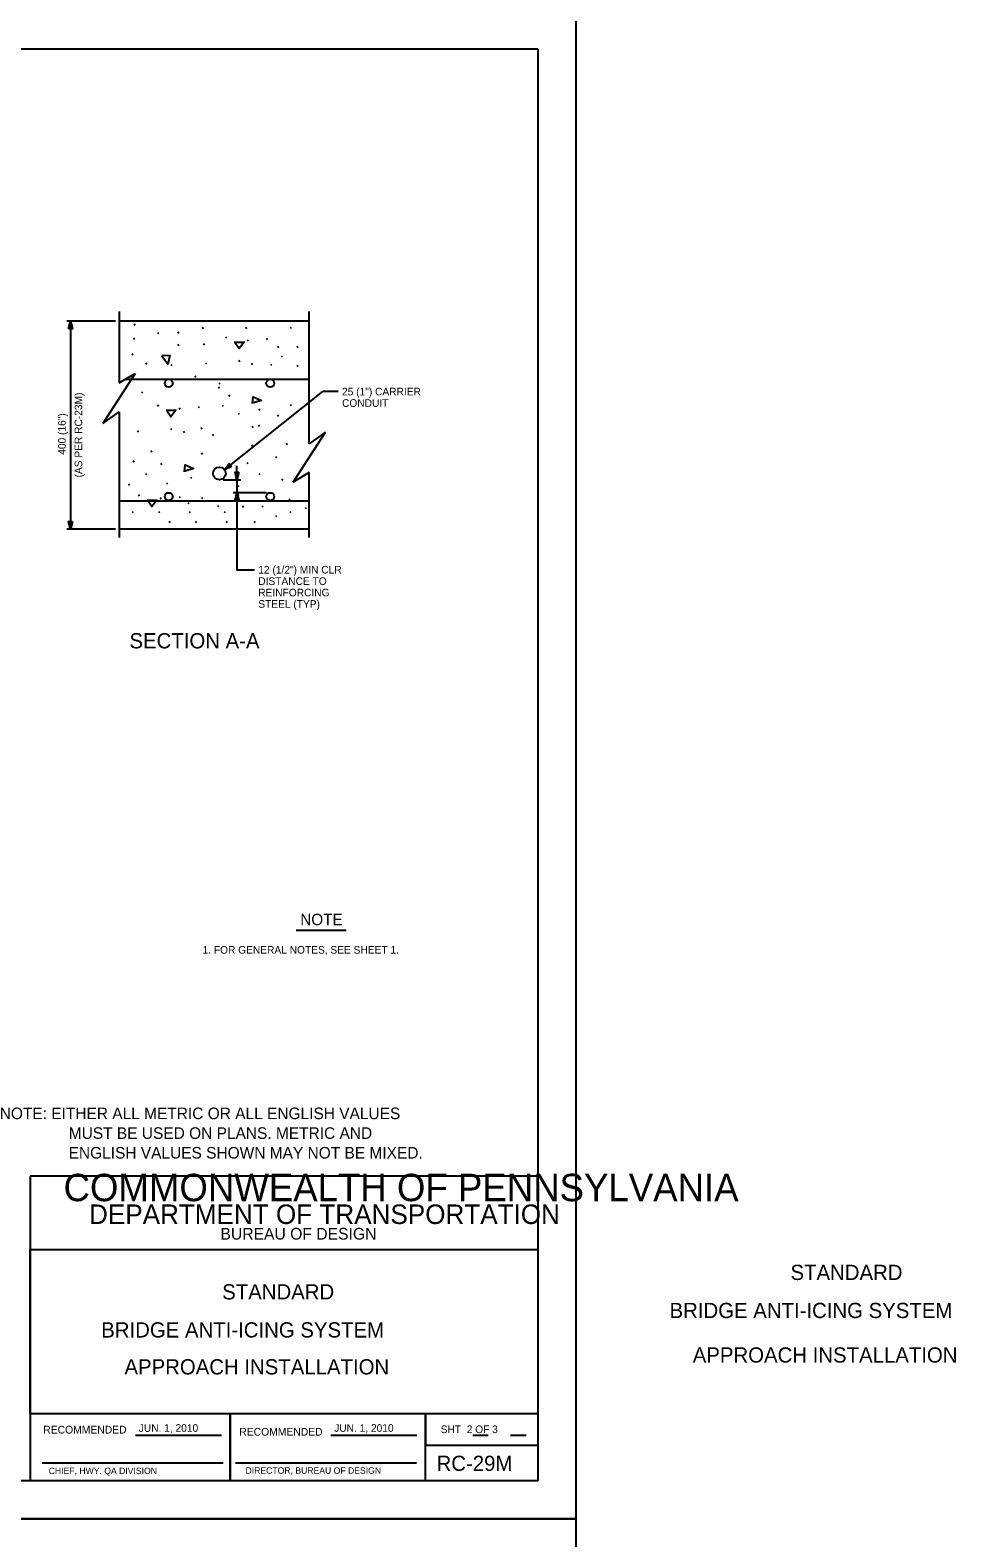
# Model space of a CAD drawing. Extents: x 3239 to 4230, y -4276 to -2494.
# Drawn here: x 3865 to 4230, y -3690 to -3096 of the extents above; entities that cross this region are included whole.
import ezdxf

# ---------------------------------------------------------------- set-up
doc = ezdxf.new("R2010")
doc.units = 0
for name, color, linetype in [('1', 7, 'Continuous'), ('2', 7, 'Continuous'), ('40', 7, 'Continuous'), ('PLT-BNDY', 7, 'Continuous')]:
    doc.layers.add(name, color=color, linetype=linetype)

msp = doc.modelspace()

# ---------------------------------------------------------------- linework, layer by layer
at = {"layer": '1'}
for p, q in [((4065.03, -3547.29), (3865.03, -3547.29)), ((3865.03, -3547.29), (3865.03, -3667.29)), ((3865.03, -3640.93), (3865.03, -3576.25)), ((3865.03, -3576.25), (4065.03, -3576.25)), ((4065.03, -3640.93), (3865.03, -3640.93)), ((3943.83, -3667.29), (3943.83, -3640.93)), ((3943.83, -3640.93), (3943.83, -3667.29)), ((4020.83, -3667.29), (4020.83, -3640.93)), ((4020.83, -3640.93), (4020.83, -3653.25)), ((3906.49, -3649.3), (3940.38, -3649.3)), ((3983.49, -3649.3), (4017.36, -3649.3)), ((4039.41, -3649.33), (4045.55, -3649.33)), ((4054.27, -3649.33), (4060.43, -3649.33)), ((4020.83, -3653.25), (4065.03, -3653.25)), ((3869.79, -3660.29), (3941.04, -3660.29)), ((3945.96, -3660.29), (4017.3, -3660.29))]:
    msp.add_line(p, q, dxfattribs=at)
at = {"layer": '2'}
for p, q in [((4065.03, -3103.29), (3279.03, -3103.29)), ((4065.03, -3103.29), (4065.03, -3667.29)), ((3900.15, -3206.57), (3900.15, -3234.8)), ((3974.95, -3258.76), (3974.95, -3206.57)), ((3898.65, -3210.43), (3879.45, -3210.43)), ((3880.95, -3210.43), (3880.95, -3292.43)), ((3974.95, -3210.43), (3900.15, -3210.43)), ((3906.02, -3211.97), (3906.49, -3211.6)), ((3932.81, -3213.26), (3933.28, -3212.89)), ((3949.89, -3213.26), (3950.36, -3212.89)), ((3967.55, -3213.26), (3968.02, -3212.89)), ((3905.78, -3217.46), (3906.24, -3217.09)), ((3915.28, -3215.28), (3915.74, -3214.9)), ((3923.25, -3215.13), (3923.71, -3214.76)), ((3933.38, -3219.8), (3933.85, -3219.43)), ((3942.07, -3217.03), (3942.54, -3216.66)), ((3950.65, -3218.21), (3951.11, -3217.84)), ((3958.19, -3217.65), (3958.66, -3217.28)), ((3905.11, -3223.64), (3905.58, -3223.26)), ((3923.25, -3219.98), (3923.71, -3219.61)), ((3962.51, -3220.74), (3962.97, -3220.37)), ((3964.03, -3224.49), (3964.49, -3224.11)), ((3970.11, -3220.74), (3970.58, -3220.37)), ((3906.39, -3231.01), (3893.65, -3250.75)), ((3900.15, -3234.8), (3906.39, -3231.01)), ((3910.67, -3227.42), (3911.14, -3227.05)), ((3920.54, -3227.9), (3921.01, -3227.53)), ((3934.2, -3227.21), (3934.66, -3226.83)), ((3947.29, -3226.32), (3947.76, -3225.95)), ((3952.3, -3227.49), (3952.76, -3227.12)), ((3959.82, -3227.76), (3960.28, -3227.39)), ((3970.11, -3228.23), (3970.58, -3227.86)), ((3902.83, -3233.25), (3974.95, -3233.25)), ((3929.96, -3232.47), (3930.42, -3232.1)), ((3939.28, -3236.85), (3939.74, -3236.48)), ((3939.46, -3235.08), (3939.93, -3234.71)), ((3908.99, -3238.71), (3909.45, -3238.34)), ((3941.61, -3268.95), (3980.42, -3238.19)), ((3943.37, -3240.01), (3943.84, -3239.64)), ((3986.42, -3238.19), (3980.42, -3238.19)), ((3893.65, -3250.75), (3900.15, -3246.13)), ((3900.15, -3246.13), (3900.15, -3295.62)), ((3915.23, -3243.87), (3915.7, -3243.5)), ((3923.81, -3245.05), (3924.27, -3244.68)), ((3931.35, -3244.49), (3931.82, -3244.12)), ((3940.76, -3243.93), (3941.23, -3243.56)), ((3947.1, -3247.1), (3947.56, -3246.72)), ((3955.16, -3245.47), (3955.63, -3245.09)), ((3962.51, -3247.89), (3962.97, -3247.52)), ((3967.58, -3243.63), (3968.04, -3243.25)), ((3907.36, -3254.04), (3907.82, -3253.67)), ((3920.45, -3253.16), (3920.92, -3252.79)), ((3925.46, -3254.33), (3925.93, -3253.95)), ((3932.28, -3252.78), (3932.75, -3252.41)), ((3936.93, -3255.46), (3937.4, -3255.08)), ((3952.55, -3252.36), (3953.02, -3251.99)), ((3955.07, -3251.8), (3955.53, -3251.43)), ((3968.71, -3273.88), (3981.44, -3254.14)), ((3981.44, -3254.14), (3974.95, -3258.76)), ((3952.3, -3259.66), (3952.76, -3259.28)), ((3965.95, -3258.96), (3966.41, -3258.58)), ((3905.66, -3265.8), (3906.12, -3265.43)), ((3912.62, -3261.92), (3913.09, -3261.55)), ((3916.53, -3266.85), (3917, -3266.48)), ((3932.56, -3262.85), (3933.03, -3262.47)), ((3950.48, -3266.5), (3950.94, -3266.13)), ((3961.71, -3264.22), (3962.17, -3263.85)), ((3910.57, -3270.83), (3911.04, -3270.46)), ((3928.32, -3272.3), (3928.79, -3271.93)), ((3946.5, -3272.79), (3946.5, -3267.43)), ((3946.5, -3272.79), (3946.5, -3308.5)), ((3955.26, -3270.83), (3955.72, -3270.46)), ((3964.26, -3273.05), (3964.73, -3272.68)), ((3974.95, -3270.1), (3968.71, -3273.88)), ((3974.95, -3295.62), (3974.95, -3270.1)), ((3903.79, -3275.04), (3904.25, -3274.67)), ((3918.88, -3274.58), (3919.34, -3274.2)), ((3941.1, -3272.94), (3948, -3272.94)), ((3958.12, -3278.02), (3945, -3278.02)), ((3946.98, -3275.62), (3947.45, -3275.25)), ((3946.98, -3279.05), (3947.45, -3278.68)), ((3900.15, -3281.28), (3974.95, -3281.28)), ((3907.73, -3279.25), (3908.2, -3278.88)), ((3916.31, -3280.44), (3916.77, -3280.06)), ((3923.85, -3279.88), (3924.32, -3279.5)), ((3927.25, -3282.24), (3927.71, -3281.87)), ((3932.63, -3280.3), (3933.1, -3279.93)), ((3938.97, -3283.47), (3939.44, -3283.1)), ((3948.71, -3283.7), (3949.17, -3283.33)), ((3956.39, -3283.62), (3956.86, -3283.24)), ((3967.07, -3280.78), (3967.54, -3280.41)), ((3973.5, -3284.29), (3973.97, -3283.92)), ((3905.31, -3285.81), (3905.77, -3285.44)), ((3915.72, -3285.81), (3916.18, -3285.44)), ((3919.81, -3289.79), (3920.28, -3289.42)), ((3927.77, -3285.81), (3928.23, -3285.44)), ((3930.22, -3289.79), (3930.69, -3289.42)), ((3941.57, -3285.81), (3942.04, -3285.44)), ((3942.27, -3289.79), (3942.74, -3289.42)), ((3953.35, -3289.78), (3953.82, -3289.4)), ((3961.81, -3287.45), (3962.27, -3287.08)), ((3967.42, -3285.81), (3967.89, -3285.44)), ((3898.65, -3292.43), (3879.45, -3292.43)), ((3974.95, -3292.43), (3900.15, -3292.43)), ((3953.46, -3308.5), (3946.5, -3308.5)), ((3969.81, -3450.39), (3989.55, -3450.39)), ((4065.03, -3667.29), (3279.03, -3667.29))]:
    msp.add_line(p, q, dxfattribs=at)
for points in [[(3880.2, -3213.43), (3880.95, -3210.43), (3881.7, -3213.43)], [(3944.43, -3267.68), (3941.61, -3268.95), (3943.49, -3266.5)], [(3947.25, -3269.94), (3946.5, -3272.94), (3945.75, -3269.94)], [(3945.75, -3281.02), (3946.5, -3278.02), (3947.25, -3281.02)], [(3881.7, -3289.43), (3880.95, -3292.43), (3880.2, -3289.43)]]:
    msp.add_lwpolyline(points, close=True, dxfattribs=at)
for points in [[(3945.44, -3218.68), (3949.31, -3218.72), (3947.35, -3221.24), (3945.72, -3218.96)], [(3917.09, -3223.88), (3920.02, -3224.02), (3919.23, -3227.42), (3916.81, -3224.16)], [(3952.69, -3242.9), (3952.97, -3240.2), (3956.23, -3241.69), (3952.92, -3242.67)], [(3918.6, -3245.52), (3922.47, -3245.56), (3920.51, -3248.08), (3918.88, -3245.8)], [(3925.85, -3269.74), (3926.13, -3267.04), (3929.39, -3268.53), (3926.08, -3269.51)], [(3911.1, -3280.9), (3914.97, -3280.95), (3913.01, -3283.46), (3911.38, -3281.18)]]:
    msp.add_lwpolyline(points, dxfattribs=at)
for centre, radius in [((3919.62, -3234.89), 1.56), ((3959.62, -3234.89), 1.56), ((3939.6, -3270.44), 2.5), ((3919.62, -3279.57), 1.56), ((3959.62, -3279.57), 1.56)]:
    msp.add_circle(centre, radius, dxfattribs=at)
at = {"layer": 'PLT-BNDY'}
for points in [[(3239.03, -3088.29), (4080.03, -3088.29), (4080.03, -3682.29), (3239.03, -3682.29)], [(3239.03, -3682.29), (4080.03, -3682.29), (4080.03, -4276.29), (3239.03, -4276.29)]]:
    msp.add_lwpolyline(points, close=True, dxfattribs=at)

# ---------------------------------------------------------------- texts
at = {"layer": '1'}
for s, height, p in [('COMMONWEALTH OF PENNSYLVANIA', 10.7834, (3878.18, -3557.15)), ('DEPARTMENT OF TRANSPORTATION', 7.6843, (3888.24, -3566.14)), ('BUREAU OF DESIGN', 4.6221, (3940.01, -3572.3)), ('RECOMMENDED', 3.048, (3870.19, -3648.7)), ('JUN. 1, 2010', 3, (3907.83, -3648.01)), ('RECOMMENDED', 3.048, (3947.43, -3649.53)), ('JUN. 1, 2010', 3, (3984.83, -3648.01)), ('APPROVED', 0.0192, (3908.05, -3649.36)), ('CHIEF, HWY. QA DIVISION', 2.54, (3872.34, -3664.67)), ('DIRECTOR, BUREAU OF DESIGN', 2.54, (3949.9, -3664.55))]:
    msp.add_text(s, height=height, dxfattribs=at).set_placement(p)
at = {"layer": '2'}
for s, height, p in [('25 (1") CARRIER', 3, (3987.92, -3239.69)), ('CONDUIT', 3, (3987.92, -3244.19)), ('12 (1/2") MIN CLR', 3, (3954.92, -3309.86)), ('DISTANCE TO', 3, (3954.92, -3314.36)), ('STEEL (TYP)', 3, (3954.92, -3323.36)), ('REINFORCING', 3, (3954.92, -3318.86)), ('SECTION A-A', 6, (3904.15, -3339.36)), ('NOTE', 4.5, (3971.46, -3448.41)), ('1. FOR GENERAL NOTES, SEE SHEET 1.', 3, (3932.96, -3459.63)), ('STANDARD', 6, (4164.64, -3588.2)), ('STANDARD', 6, (3940.7, -3595.86)), ('BRIDGE ANTI-ICING SYSTEM', 6, (4116.98, -3603.2)), ('BRIDGE ANTI-ICING SYSTEM', 6, (3893.04, -3610.86)), ('APPROACH INSTALLATION', 6, (4126.12, -3620.74)), ('APPROACH INSTALLATION', 6, (3902.18, -3625.41)), ('SHT  2 OF 3', 3, (4026.79, -3648.52)), ('RC-29M', 6, (4025.19, -3663.43))]:
    msp.add_text(s, height=height, dxfattribs=at).set_placement(p)
for s, p in [('(AS PER RC-23M)', (3885.54, -3272.01)), ('400 (16")', (3879.04, -3263.08))]:
    msp.add_text(s, height=3, rotation=90, dxfattribs=at).set_placement(p)
at = {"layer": '40'}
for s, p in [('NOTE: EITHER ALL METRIC OR ALL ENGLISH VALUES', (3853.02, -3524.83)), ('MUST BE USED ON PLANS. METRIC AND', (3880.24, -3532.6)), ('ENGLISH VALUES SHOWN MAY NOT BE MIXED.', (3880.17, -3540.36))]:
    msp.add_text(s, height=4.5587, dxfattribs=at).set_placement(p)

doc.saveas('drawing.dxf')
